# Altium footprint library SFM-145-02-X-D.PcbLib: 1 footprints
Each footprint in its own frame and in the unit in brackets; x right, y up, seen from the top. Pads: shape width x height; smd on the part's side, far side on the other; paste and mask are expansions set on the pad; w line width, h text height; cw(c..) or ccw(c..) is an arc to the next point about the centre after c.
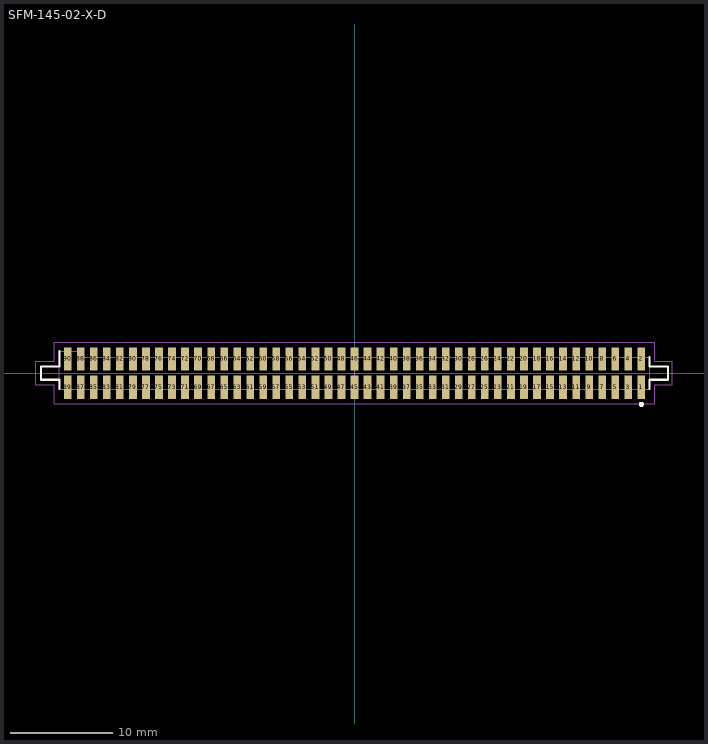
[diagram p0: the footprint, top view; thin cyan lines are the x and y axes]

## SFM-145-02-X-D [mm] "1.27mm pitch, 90 pin, socket strip; SMT"
height 4.57
pads (90):
  rect 0.75x2.25 smd mask+0: 1(27.94,-1.375) 2(27.94,1.375) 3(26.67,-1.375) 4(26.67,1.375) 5(25.4,-1.375) 6(25.4,1.375) 7(24.13,-1.375) 8(24.13,1.375) 9(22.86,-1.375) 10(22.86,1.375) 11(21.59,-1.375) 12(21.59,1.375) 13(20.32,-1.375) 14(20.32,1.375) 15(19.05,-1.375) 16(19.05,1.375) 17(17.78,-1.375) 18(17.78,1.375) 19(16.51,-1.375) 20(16.51,1.375) 21(15.24,-1.375) 22(15.24,1.375) 23(13.97,-1.375) 24(13.97,1.375) 25(12.7,-1.375) 26(12.7,1.375) 27(11.43,-1.375) 28(11.43,1.375) 29(10.16,-1.375) 30(10.16,1.375) 31(8.89,-1.375) 32(8.89,1.375) 33(7.62,-1.375) 34(7.62,1.375) 35(6.35,-1.375) 36(6.35,1.375) 37(5.08,-1.375) 38(5.08,1.375) 39(3.81,-1.375) 40(3.81,1.375) 41(2.54,-1.375) 42(2.54,1.375) 43(1.27,-1.375) 44(1.27,1.375) 45(0,-1.375) 46(0,1.375) 47(-1.27,-1.375) 48(-1.27,1.375) 49(-2.54,-1.375) 50(-2.54,1.375) 51(-3.81,-1.375) 52(-3.81,1.375) 53(-5.08,-1.375) 54(-5.08,1.375) 55(-6.35,-1.375) 56(-6.35,1.375) 57(-7.62,-1.375) 58(-7.62,1.375) 59(-8.89,-1.375) 60(-8.89,1.375) 61(-10.16,-1.375) 62(-10.16,1.375) 63(-11.43,-1.375) 64(-11.43,1.375) 65(-12.7,-1.375) 66(-12.7,1.375) 67(-13.97,-1.375) 68(-13.97,1.375) 69(-15.24,-1.375) 70(-15.24,1.375) 71(-16.51,-1.375) 72(-16.51,1.375) 73(-17.78,-1.375) 74(-17.78,1.375) 75(-19.05,-1.375) 76(-19.05,1.375) 77(-20.32,-1.375) 78(-20.32,1.375) 79(-21.59,-1.375) 80(-21.59,1.375) 81(-22.86,-1.375) 82(-22.86,1.375) 83(-24.13,-1.375) 84(-24.13,1.375) 85(-25.4,-1.375) 86(-25.4,1.375) 87(-26.67,-1.375) 88(-26.67,1.375) 89(-27.94,-1.375) 90(-27.94,1.375)
Top Overlay:
  circle w0.25: c27.95,-3.05 r0.125
  lines w0.2: -28.75,-1.55 -28.75,-0.65 -30.55,-0.65 -30.55,0.65 -28.75,0.65 -28.75,2.15 ; 28.75,-1.55 28.75,-0.65 30.55,-0.65 30.55,0.65 28.75,0.65 28.75,1.55
Mechanical 12:
  lines w0.001: -30.55,-0.65 -30.55,0.65 -28.75,0.65 -28.75,2.15 -26.7,2.15 -26.7,1.55 28.75,1.55 28.75,0.65 30.55,0.65 30.55,-0.65 28.75,-0.65 28.75,-1.55 -28.75,-1.55 -28.75,-0.65 -30.55,-0.65
Mechanical 13:
  lines w0.1: -28.75,-0.65 -28.75,0.65 ; -28.75,-0.65 -30.55,-0.65 -30.55,0.65 -28.75,0.65 ; -28.75,-0.65 -28.75,-1.55 28.75,-1.55 28.75,-0.65 ; -28.75,0.65 -28.75,2.15 -26.7,2.15 -26.7,1.55 28.75,1.55 28.75,0.65 ; 28.75,-0.65 28.75,0.65 ; 28.75,-0.65 30.55,-0.65 30.55,0.65 28.75,0.65
  text ".Designator" at 0,-0.127 h1.52
Mechanical 15:
  lines w0.05: -31.05,-1.15 -29.25,-1.15 -29.25,-3 29.25,-3 29.25,-1.15 30.95,-1.15 30.95,1.15 29.25,1.15 29.25,3 -29.25,3 -29.25,1.15 -31.05,1.15 -31.05,-1.15 ; -0.5,0 0.5,0 -0.5,0 ; 0,-0.5 0,0.5 0,-0.5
